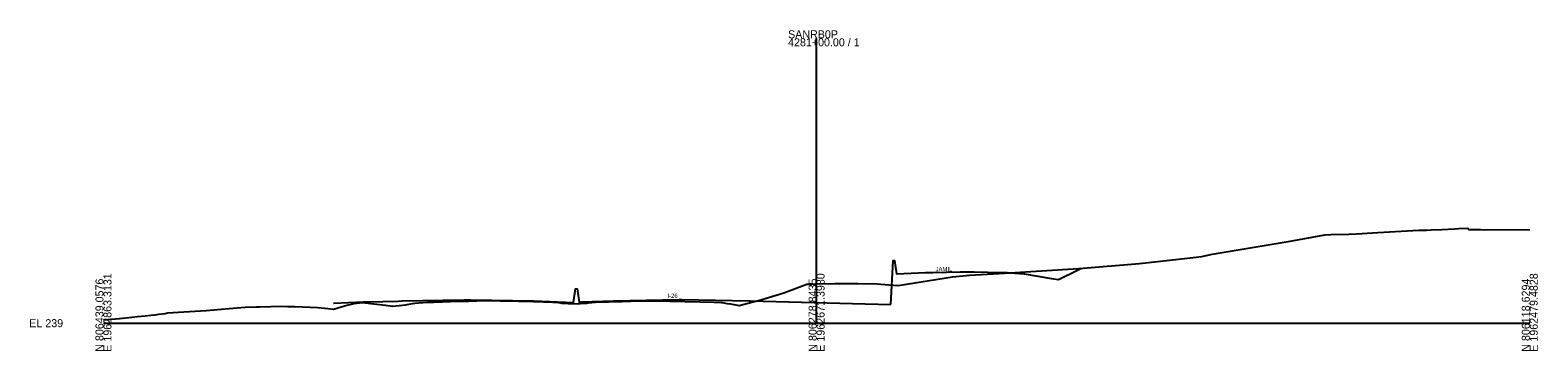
# Model space of a CAD drawing. Extents: x 1995641 to 1997170, y 790368 to 809963.
# Drawn here: x 1995641 to 1996170, y 791868 to 791981 of the extents above; entities that cross this region are included whole.
import ezdxf

# ---------------------------------------------------------------- set-up
doc = ezdxf.new("R2010")
doc.units = 0
for name, color, linetype in [('Default', 7, 'Continuous'), ('RD_GPK_XS_Cell', 7, 'Continuous'), ('RD_Sketch1', 7, 'Continuous'), ('RD_XS_ExGround', 7, 'Continuous'), ('RD_XS_Pave', 7, 'Continuous')]:
    doc.layers.add(name, color=color, linetype=linetype)

msp = doc.modelspace()

# ---------------------------------------------------------------- linework, layer by layer
at = {"layer": 'RD_GPK_XS_Cell'}
for p, q in [((1995917.06, 791878.11), (1995917.06, 791977.91)), ((1995667.06, 791878.11), (1995917.06, 791878.11)), ((1995917.06, 791878.11), (1996167.06, 791878.11))]:
    msp.add_line(p, q, dxfattribs=at)
at = {"layer": 'RD_XS_ExGround'}
msp.add_lwpolyline([(1995667.06, 791879.24), (1995668.44, 791879.35), (1995672.73, 791879.71), (1995676.95, 791880.25), (1995679.05, 791880.44), (1995681.67, 791880.7), (1995683.62, 791880.9), (1995685.17, 791881.08), (1995686.47, 791881.24), (1995687.61, 791881.39), (1995688.65, 791881.54), (1995689.62, 791881.69), (1995695.29, 791882.12), (1995703.02, 791882.6), (1995713.8, 791883.5), (1995716.7, 791883.7), (1995720.7, 791883.78), (1995721.45, 791883.78), (1995721.82, 791883.81), (1995729.59, 791884.03), (1995731.62, 791884), (1995734.16, 791883.98), (1995742.27, 791883.62), (1995745.7, 791883.2), (1995747.71, 791883), (1995751.57, 791884.24), (1995754.92, 791885.04), (1995757.72, 791885.39), (1995765.92, 791884.4), (1995768.54, 791884.08), (1995772.96, 791884.54), (1995775.39, 791884.99), (1995776.17, 791885.06), (1995780.56, 791885.42), (1995782.92, 791885.5), (1995788.7, 791885.68), (1995795.07, 791885.86), (1995800.95, 791886.03), (1995806.13, 791885.95), (1995812.68, 791885.85), (1995817.79, 791885.69), (1995824.61, 791885.5), (1995826.47, 791885.37), (1995827, 791885.33), (1995827.8, 791885.15), (1995829.17, 791885.07), (1995829.98, 791885.03), (1995830.44, 791885.01), (1995831.86, 791884.97), (1995833.34, 791884.94), (1995834.28, 791885.01), (1995836.42, 791885.15), (1995836.62, 791885.22), (1995837.04, 791885.22), (1995837.27, 791885.33), (1995838.21, 791885.39), (1995839.54, 791885.47), (1995848.75, 791885.73), (1995851.9, 791885.82), (1995862.09, 791885.88), (1995864, 791885.89), (1995865.64, 791885.86), (1995876.27, 791885.62), (1995881.12, 791885.45), (1995883.66, 791885.37), (1995884.05, 791885.3), (1995885.62, 791885.05), (1995886.9, 791884.84), (1995889.92, 791884.35), (1995897.56, 791886.32), (1995905.59, 791888.73), (1995913.65, 791891.75), (1995915.35, 791891.82), (1995917.16, 791891.85), (1995923.49, 791891.96), (1995927.71, 791892.04), (1995931.49, 791891.96), (1995938.15, 791891.87), (1995942.48, 791891.49), (1995945.63, 791891.28), (1995964.72, 791894.31), (1995970.62, 791894.93), (1995981.01, 791895.56), (1996008.88, 791897.24), (1996009.86, 791897.3), (1996010.55, 791897.36), (1996030.21, 791898.96), (1996046.03, 791900.78), (1996052.12, 791901.5), (1996055.69, 791902.26), (1996083.08, 791906.83), (1996092.12, 791908.52), (1996095.17, 791909.09), (1996097.28, 791909.18), (1996103.6, 791909.32), (1996106.28, 791909.36), (1996113.76, 791909.82), (1996122.01, 791910.33), (1996128.23, 791910.65), (1996130.92, 791910.74), (1996132.5, 791910.85), (1996136.24, 791910.95), (1996140.8, 791911.21), (1996142.09, 791911.24), (1996145.41, 791911.38), (1996145.73, 791910.89), (1996148.56, 791910.91), (1996149.96, 791910.9), (1996167.06, 791910.77)], dxfattribs=at)
at = {"layer": 'RD_XS_Pave'}
for points in [[(1995943.1, 791884.68), (1995943.86, 791900.07), (1995944.36, 791900.07), (1995945.11, 791895.4), (1995955.28, 791895.81), (1995957.86, 791895.91), (1995967.43, 791896.1), (1995969.86, 791896.15), (1995972.3, 791896.1), (1995981.86, 791895.91), (1995983.46, 791895.88), (1995983.86, 791895.87), (1995985.08, 791895.77), (1995989.86, 791895.39), (1995999.43, 791893.8), (1996001.86, 791893.39), (1996008.25, 791896.58), (1996009.94, 791897.43)], [(1995747.75, 791885.12), (1995758.22, 791885.53), (1995759.76, 791885.59), (1995770.35, 791885.85), (1995771.77, 791885.88), (1995793.38, 791886.3), (1995795.79, 791886.34), (1995817.87, 791885.88), (1995819.81, 791885.84), (1995820.75, 791885.81), (1995831.82, 791885.36), (1995832.57, 791890.18), (1995833.07, 791890.18), (1995833.82, 791885.51), (1995834.63, 791885.54), (1995845.83, 791885.98), (1995868.88, 791886.42), (1995869.85, 791886.44), (1995893.37, 791885.95), (1995893.87, 791885.94), (1995943.1, 791884.68)]]:
    msp.add_lwpolyline(points, dxfattribs=at)

# ---------------------------------------------------------------- texts
at = {"layer": 'Default'}
msp.add_text('-', height=0.0001, dxfattribs=at).set_placement((1995667.06, 791878.11))
msp.add_text('-', height=0.0001, dxfattribs=at).set_placement((1995667.06, 791878.11))
at = {"layer": 'RD_GPK_XS_Cell'}
for s, p in [('SANRB0P', (1995907.06, 791977.91)), ('4281+00.00 / 1', (1995907.06, 791975.11)), ('EL 239', (1995641.06, 791876.71))]:
    msp.add_text(s, height=2.8, dxfattribs=at).set_placement(p)
for s, p in [('E 1962863.3131', (1995669.86, 791868.11)), ('E 1962671.3980', (1995919.86, 791868.11)), ('E 1962479.4828', (1996169.86, 791868.11)), ('N 806439.0576', (1995667.06, 791868.11)), ('N 806278.8435', (1995917.06, 791868.11)), ('N 806118.6294', (1996167.06, 791868.11))]:
    msp.add_text(s, height=2.8, rotation=90, dxfattribs=at).set_placement(p)
at = {"layer": 'RD_Sketch1'}
msp.add_text('252.73', height=0.1, dxfattribs=at).set_placement((1995916.85, 791891.75))
at = {"layer": 'RD_XS_Pave'}
for s, p in [('JAMIL', (1995958.77, 791896.29)), ('I-26', (1995864.78, 791886.95))]:
    msp.add_text(s, height=1.5, dxfattribs=at).set_placement(p)

doc.saveas('drawing.dxf')
